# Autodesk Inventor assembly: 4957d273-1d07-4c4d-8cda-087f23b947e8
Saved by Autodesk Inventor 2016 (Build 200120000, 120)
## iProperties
Created: 2016-09
Part Number: 4957d273-1d07-4c4d-8cda-087f23b947e8
Document SubType Name: Assembly
Designer: Administrator
Author: Administrator
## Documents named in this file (13)
- c:\worker\convert-fusion-aug-2016\tmp\job-1\19\output\files\b1646d38-3d95-4128-a552-c87d2d1b62c9\4957d273-1d07-4c4d-8cda-087f23b947e8.iam
- c:\worker\convert-fusion-aug-2016\tmp\job-1\19\output\files\b1646d38-3d95-4128-a552-c87d2d1b62c9\board.ipt
- c:\worker\convert-fusion-aug-2016\tmp\job-1\19\output\files\b1646d38-3d95-4128-a552-c87d2d1b62c9\micro_usb (1).iam
- c:\worker\convert-fusion-aug-2016\tmp\job-1\19\output\files\b1646d38-3d95-4128-a552-c87d2d1b62c9\qfp16 v2.iam
- c:\worker\convert-fusion-aug-2016\tmp\job-1\19\output\files\b1646d38-3d95-4128-a552-c87d2d1b62c9\diode_0402 v1.ipt
- c:\worker\convert-fusion-aug-2016\tmp\job-1\19\output\files\b1646d38-3d95-4128-a552-c87d2d1b62c9\cap0603_03 v3.ipt
- c:\worker\convert-fusion-aug-2016\tmp\job-1\19\output\files\b1646d38-3d95-4128-a552-c87d2d1b62c9\crystal_dfn4 v8.iam
- c:\worker\convert-fusion-aug-2016\tmp\job-1\19\output\files\b1646d38-3d95-4128-a552-c87d2d1b62c9\smt_tactile_button_2 v2.iam
- c:\worker\convert-fusion-aug-2016\tmp\job-1\19\output\files\b1646d38-3d95-4128-a552-c87d2d1b62c9\qfn48 v2.ipt
- c:\worker\convert-fusion-aug-2016\tmp\job-1\19\output\files\b1646d38-3d95-4128-a552-c87d2d1b62c9\cap0402 v2.ipt
- c:\worker\convert-fusion-aug-2016\tmp\job-1\19\output\files\b1646d38-3d95-4128-a552-c87d2d1b62c9\resistor_0805 v2.ipt
- c:\worker\convert-fusion-aug-2016\tmp\job-1\19\output\files\b1646d38-3d95-4128-a552-c87d2d1b62c9\smt_led_0603 v2.ipt
- c:\worker\convert-fusion-aug-2016\tmp\job-1\19\output\files\b1646d38-3d95-4128-a552-c87d2d1b62c9\sop23 v2.iam
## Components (21 placed, 14 different names)
1. board:1
2. micro_usb (1):1 [sub-assembly]
3. qfp16 v2:1 [sub-assembly]
4. diode_0402 v1:1
5. cap0603_03 v3:1
6. diode_0402 v1:1:1
7. diode_0402 v1:2
8. cap0603_03 v3:2
9. diode_0402 v1:3
10. crystal_dfn4 v8:1 [sub-assembly]
11. smt_tactile_button_2 v2:1 [sub-assembly]
12. qfn48 v2:1
13. cap0402 v2:1
14. cap0402 v2:1:1
15. cap0402 v2:2
16. cap0402 v2:3
17. cap0402 v2:4
18. cap0402 v2:5
19. resistor_0805 v2:1
20. smt_led_0603 v2:1
21. sop23 v2:1 [sub-assembly]
